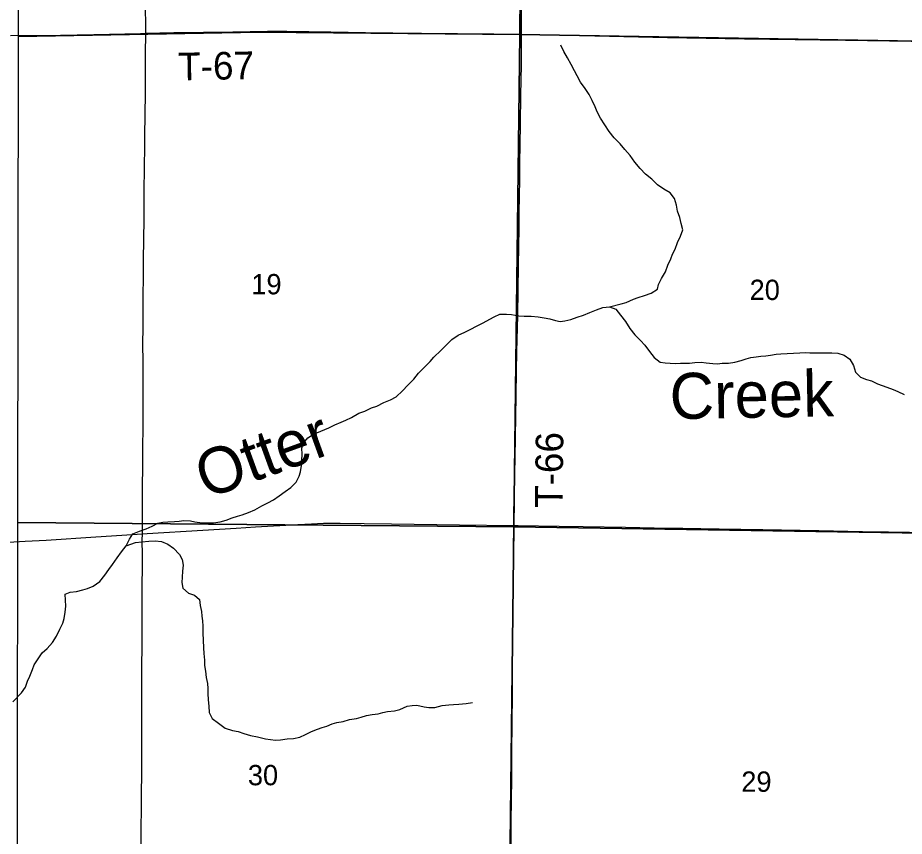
# Model space of a CAD drawing. Extents: x 0 to 45.9, y 0 to 22.
# Drawn here: x 5.48 to 7.305, y 15.053 to 16.738 of the extents above; entities that cross this region are included whole.
import ezdxf

# ---------------------------------------------------------------- set-up
doc = ezdxf.new("R2010")
doc.units = 0
for name, color, linetype in [('GM_X_County_Road', 7, 'Continuous'), ('GM_X_Minor_River', 7, 'Continuous'), ('GM_X_Minor_River_Text', 7, 'Continuous'), ('GM_X_Section', 7, 'Continuous'), ('GM_X_Section_Text', 7, 'Continuous'), ('GM_X_State_Route', 7, 'Continuous'), ('GM_X_Township_Road', 7, 'Continuous'), ('GM_X_Township_Road_Text', 7, 'Continuous')]:
    doc.layers.add(name, color=color, linetype=linetype)

msp = doc.modelspace()

# ---------------------------------------------------------------- linework, layer by layer
at = {"layer": 'GM_X_County_Road'}
msp.add_lwpolyline([(6.4922, 14.6848), (6.4925, 14.7031), (6.4931, 14.7497), (6.4935, 14.7963), (6.4943, 14.9175), (6.495, 14.9858), (6.496, 15.079), (6.4964, 15.1318), (6.497, 15.166), (6.4974, 15.1877), (6.4974, 15.225), (6.4976, 15.2871), (6.4982, 15.343), (6.4985, 15.3834), (6.4988, 15.4145), (6.499, 15.4642), (6.4995, 15.5077), (6.5001, 15.5667), (6.5003, 15.6009), (6.5006, 15.6413), (6.5009, 15.6926)], dxfattribs=at)
at = {"layer": 'GM_X_Minor_River'}
for points in [[(6.6979, 16.1429), (6.7221, 16.1487), (6.7324, 16.1517), (6.7475, 16.1582), (6.7574, 16.1621), (6.7699, 16.1663), (6.7839, 16.1705), (6.7967, 16.1789), (6.799, 16.1884), (6.8054, 16.2009), (6.8133, 16.215), (6.8182, 16.2283), (6.8242, 16.2416), (6.8276, 16.251), (6.8333, 16.2613), (6.8381, 16.275), (6.8442, 16.2883), (6.8487, 16.3012), (6.8456, 16.3141), (6.8425, 16.3266), (6.8383, 16.3394), (6.836, 16.3523), (6.8317, 16.366), (6.8226, 16.3777), (6.8101, 16.3852), (6.7971, 16.3939), (6.7853, 16.4056), (6.7724, 16.4158), (6.761, 16.4276), (6.7499, 16.4404), (6.7404, 16.454), (6.7297, 16.4669), (6.7198, 16.4786), (6.708, 16.4903), (6.6977, 16.5036), (6.6886, 16.5176), (6.6798, 16.5308), (6.6729, 16.5444), (6.6683, 16.5543), (6.6622, 16.5675), (6.6561, 16.5797), (6.6481, 16.5925), (6.6386, 16.605), (6.6313, 16.6183), (6.6263, 16.6285), (6.6195, 16.6414), (6.6118, 16.6554), (6.6042, 16.6686), (6.5977, 16.6811)], [(5.47, 15.3291), (5.4883, 15.3481), (5.4962, 15.3598), (5.5007, 15.372), (5.5049, 15.3819), (5.5105, 15.3959), (5.5143, 15.4054), (5.5222, 15.418), (5.5305, 15.4301), (5.5407, 15.4389), (5.552, 15.4518), (5.56, 15.4647), (5.5671, 15.4788), (5.5731, 15.4917), (5.5761, 15.5012), (5.578, 15.5141), (5.5791, 15.5262), (5.5783, 15.5384), (5.5782, 15.5513), (5.5881, 15.5551), (5.6014, 15.5563), (5.6146, 15.5597), (5.6241, 15.5628), (5.6358, 15.5678), (5.6491, 15.5773), (5.6593, 15.5902), (5.668, 15.6016), (5.6751, 15.6119), (5.685, 15.6256), (5.694, 15.6385), (5.7038, 15.6507), (5.7102, 15.664), (5.717, 15.6754), (5.731, 15.6811), (5.7447, 15.6857), (5.7572, 15.6911), (5.7689, 15.6972), (5.7788, 15.6995), (5.7894, 15.6999), (5.8027, 15.7007), (5.8125, 15.7015), (5.822, 15.7027), (5.8357, 15.7019), (5.8451, 15.7001), (5.8599, 15.6982), (5.8732, 15.6979), (5.8835, 15.6979), (5.8967, 15.6999), (5.9092, 15.7033), (5.9217, 15.7079), (5.9327, 15.7114), (5.9422, 15.7144), (5.9551, 15.719), (5.9683, 15.7248), (5.9824, 15.7328), (5.9952, 15.7393), (6.0066, 15.7454), (6.0183, 15.7538), (6.0308, 15.7625), (6.0422, 15.7705), (6.0531, 15.7819), (6.0595, 15.7937), (6.0621, 15.8032), (6.064, 15.8161), (6.0651, 15.8263), (6.0654, 15.8392), (6.065, 15.8518), (6.0676, 15.8616), (6.0771, 15.873), (6.0892, 15.8807), (6.104, 15.8864), (6.1202, 15.8937), (6.1327, 15.8994), (6.1456, 15.9055), (6.1555, 15.9093), (6.1672, 15.9147), (6.1823, 15.9238), (6.1949, 15.9277), (6.2081, 15.9345), (6.2195, 15.9384), (6.2335, 15.9456), (6.2471, 15.9514), (6.2592, 15.9571), (6.2721, 15.9696), (6.283, 15.9814), (6.2951, 15.9936), (6.305, 16.0058), (6.3288, 16.0298), (6.3363, 16.0393), (6.3511, 16.053), (6.3734, 16.0754), (6.3866, 16.0842), (6.4003, 16.0907), (6.4366, 16.109), (6.4605, 16.1224), (6.4722, 16.1273), (6.4859, 16.1278), (6.4965, 16.1267), (6.5113, 16.1244), (6.5227, 16.1233), (6.5367, 16.1238)], [(6.5367, 16.1238), (6.5511, 16.1219), (6.5637, 16.1201), (6.5754, 16.1178), (6.5868, 16.1148), (6.5963, 16.1126), (6.6065, 16.1138), (6.6187, 16.1168), (6.6316, 16.1211), (6.6444, 16.1256), (6.6577, 16.131), (6.6713, 16.1367), (6.6846, 16.141), (6.6979, 16.1429), (6.7108, 16.1376), (6.7207, 16.1255), (6.731, 16.1123), (6.7398, 16.0983), (6.7504, 16.085), (6.7622, 16.0737), (6.771, 16.0635), (6.7805, 16.0506), (6.79, 16.0382), (6.8026, 16.0287), (6.8125, 16.0276), (6.8227, 16.0265), (6.8329, 16.0262), (6.8439, 16.0266), (6.8629, 16.027), (6.8735, 16.0278), (6.8864, 16.0286), (6.8967, 16.0275), (6.9107, 16.026), (6.9202, 16.0253), (6.9297, 16.0265), (6.9433, 16.0269), (6.9558, 16.0285), (6.9687, 16.0319), (6.979, 16.0358), (6.9888, 16.0384), (6.9998, 16.04), (7.0097, 16.0412), (7.0199, 16.042), (7.0294, 16.0431), (7.0408, 16.0451), (7.0506, 16.0459), (7.0635, 16.0467), (7.0764, 16.0471), (7.0897, 16.0483), (7.1007, 16.0487), (7.1106, 16.0483), (7.12, 16.048), (7.1322, 16.0477), (7.142, 16.0481), (7.1553, 16.0477), (7.1678, 16.047), (7.1807, 16.0433), (7.1925, 16.035), (7.2002, 16.0221), (7.2044, 16.0085), (7.2147, 15.9979), (7.2272, 15.9934), (7.2375, 15.99), (7.2496, 15.9843), (7.2591, 15.981), (7.269, 15.9776), (7.2819, 15.9727), (7.2914, 15.9685), (7.3047, 15.9621)], [(5.7038, 15.6507), (5.7228, 15.6576), (5.7357, 15.6587), (5.7501, 15.6603), (5.763, 15.6607), (5.7759, 15.6593), (5.7892, 15.654), (5.801, 15.6457), (5.8131, 15.6328), (5.8185, 15.6222), (5.8208, 15.6105), (5.8197, 15.5987), (5.8186, 15.5858), (5.8179, 15.5752), (5.8198, 15.5635), (5.832, 15.5533), (5.8442, 15.5487), (5.8541, 15.5401), (5.856, 15.5279), (5.8583, 15.5154), (5.8595, 15.5059), (5.8603, 15.4965), (5.8611, 15.4855), (5.8611, 15.4707), (5.8616, 15.4563), (5.8628, 15.4407), (5.8632, 15.4286), (5.8644, 15.4153), (5.8648, 15.4043), (5.8664, 15.3926), (5.8683, 15.3797), (5.8706, 15.3668), (5.8718, 15.3566), (5.8718, 15.3467), (5.8723, 15.3334), (5.8738, 15.3202), (5.8746, 15.3076), (5.8807, 15.2951), (5.8937, 15.2853), (5.907, 15.2755), (5.9222, 15.2706), (5.9339, 15.2684), (5.9457, 15.2639), (5.959, 15.2598), (5.9738, 15.2575), (5.9905, 15.253), (6.011, 15.2508), (6.0212, 15.2512), (6.0349, 15.2532), (6.0478, 15.2536), (6.0611, 15.2567), (6.0724, 15.262), (6.0849, 15.2685), (6.097, 15.2731), (6.1069, 15.2766), (6.1164, 15.2796), (6.1273, 15.2842), (6.1368, 15.2869), (6.1501, 15.2888), (6.163, 15.2927), (6.1774, 15.2954), (6.1869, 15.2977), (6.1978, 15.3011), (6.2096, 15.3035), (6.2217, 15.305), (6.2316, 15.3077), (6.2414, 15.3096), (6.2555, 15.3108), (6.2665, 15.3135), (6.2816, 15.3204), (6.2922, 15.3219), (6.3017, 15.3224), (6.3165, 15.3194), (6.326, 15.3175), (6.3389, 15.3175), (6.3537, 15.3218), (6.3673, 15.323), (6.3772, 15.3241), (6.3882, 15.3249), (6.403, 15.3257), (6.4159, 15.3277)]]:
    msp.add_lwpolyline(points, dxfattribs=at)
at = {"layer": 'GM_X_Section'}
for points in [[(5.4835, 17.7031), (6.0871, 17.7131), (6.5217, 17.7114), (6.5134, 16.7036), (5.9766, 16.7084), (5.4822, 16.699)], [(6.5217, 17.7114), (7.5472, 17.6966), (7.5363, 16.6862), (6.5134, 16.7036)], [(5.4822, 16.699), (5.9766, 16.7084), (6.5134, 16.7036), (6.5014, 15.6897), (5.4804, 15.6984)], [(6.5134, 16.7036), (7.5363, 16.6862), (7.5224, 15.6742), (6.5014, 15.6897)], [(6.5014, 15.6897), (6.4893, 14.6816), (5.4789, 14.694), (5.4804, 15.6984)], [(7.5224, 15.6742), (7.4967, 14.6639), (6.4893, 14.6816), (6.5014, 15.6897)]]:
    msp.add_lwpolyline(points, close=True, dxfattribs=at)
at = {"layer": 'GM_X_State_Route'}
for points in [[(5.4608, 15.6583), (5.4954, 15.6601), (5.5388, 15.6625), (5.6411, 15.6689), (5.7368, 15.6752), (5.7466, 15.6758), (5.8613, 15.6831), (5.9296, 15.6871), (5.9699, 15.6896), (6.0567, 15.6947), (6.0847, 15.6962), (6.1095, 15.6971), (6.1437, 15.6972), (6.1935, 15.6966), (6.2494, 15.6956), (6.296, 15.695), (6.3892, 15.6938), (6.5009, 15.6926), (6.5104, 15.6925), (6.5943, 15.6913), (6.644, 15.6902), (6.731, 15.6888), (6.79, 15.6877), (6.849, 15.6867), (6.9236, 15.6853), (7.0137, 15.684), (7.1287, 15.682), (7.2187, 15.6802), (7.2685, 15.6796), (7.2725, 15.6795)], [(7.2725, 15.6795), (7.3586, 15.6779), (7.4145, 15.677), (7.4334, 15.6767)]]:
    msp.add_lwpolyline(points, dxfattribs=at)
at = {"layer": 'GM_X_Township_Road'}
for points in [[(6.5172, 16.7037), (6.5172, 16.7187), (6.5168, 16.7871), (6.5162, 16.8586), (6.516, 17.0047), (6.516, 17.0544), (6.5154, 17.0917), (6.5158, 17.1135), (6.5158, 17.1321), (6.5155, 17.1445), (6.5154, 17.1694), (6.5162, 17.2066), (6.5163, 17.2101), (6.5164, 17.2377), (6.5169, 17.2781), (6.5179, 17.3403), (6.5183, 17.3807), (6.5196, 17.4491), (6.5211, 17.5673), (6.5223, 17.6419), (6.5236, 17.7071), (6.5237, 17.7143)], [(5.7436, 16.7061), (5.7436, 16.728), (5.7435, 16.7529), (5.7438, 16.7809), (5.7443, 16.815), (5.7449, 16.8647), (5.7453, 16.9051), (5.7458, 16.9611), (5.746, 17.0015), (5.7462, 17.0387), (5.7465, 17.0947), (5.7468, 17.1537), (5.7468, 17.1879), (5.7469, 17.2044)], [(5.4653, 16.7013), (5.5685, 16.7021), (5.6369, 16.7037), (5.7332, 16.7058), (5.7436, 16.7061)], [(5.7385, 16.1598), (5.7385, 16.1658), (5.7389, 16.2031), (5.7391, 16.2187), (5.7394, 16.2434), (5.7398, 16.2775), (5.7403, 16.3272), (5.7408, 16.3707), (5.7412, 16.4391), (5.7416, 16.4639), (5.7422, 16.495), (5.743, 16.582), (5.7432, 16.6379), (5.7434, 16.669), (5.7436, 16.7001), (5.7436, 16.7061)], [(5.7436, 16.7061), (5.8015, 16.7077), (5.9227, 16.7089), (5.994, 16.7101), (6.0344, 16.71), (6.1245, 16.7091), (6.196, 16.7078), (6.2519, 16.7071), (6.3109, 16.7062), (6.4601, 16.7046), (6.5172, 16.7037)], [(6.5009, 15.6926), (6.501, 15.699), (6.5015, 15.7208), (6.5025, 15.7674), (6.5039, 15.8327), (6.5054, 15.9166), (6.5061, 15.9602), (6.5067, 16.0099), (6.5075, 16.0503), (6.5093, 16.1249), (6.5102, 16.1777), (6.511, 16.2275), (6.5121, 16.3052), (6.5123, 16.3207), (6.5125, 16.3363), (6.5133, 16.4047), (6.5138, 16.4389), (6.5144, 16.4762), (6.5152, 16.5197), (6.5159, 16.5788), (6.5169, 16.6409), (6.5172, 16.6689), (6.5172, 16.7037)], [(6.5172, 16.7037), (6.5315, 16.7034), (6.5906, 16.7026), (6.6682, 16.7007), (6.8174, 16.6975), (6.9758, 16.6945), (7.184, 16.6915), (7.3642, 16.689), (7.4574, 16.6876), (7.5369, 16.6872), (7.5398, 16.6872)], [(5.7368, 15.6752), (5.7368, 15.6811), (5.7369, 15.7152), (5.7371, 15.7712), (5.7375, 15.8147), (5.7382, 15.9327), (5.7383, 16.0322), (5.738, 16.0632), (5.7383, 16.1036), (5.7385, 16.1598)], [(6.4922, 14.6848), (6.4925, 14.7031), (6.4931, 14.7497), (6.4935, 14.7963), (6.4943, 14.9175), (6.495, 14.9858), (6.496, 15.079), (6.4964, 15.1318), (6.497, 15.166), (6.4974, 15.1877), (6.4974, 15.225), (6.4976, 15.2871), (6.4982, 15.343), (6.4985, 15.3834), (6.4988, 15.4145), (6.499, 15.4642), (6.4995, 15.5077), (6.5001, 15.5667), (6.5003, 15.6009), (6.5006, 15.6413), (6.5009, 15.6926)], [(5.7321, 14.6921), (5.7322, 14.7241), (5.7325, 14.8017), (5.7329, 14.8483), (5.7336, 14.9322), (5.7339, 14.9851), (5.7341, 15.0223), (5.7345, 15.0565), (5.7349, 15.1218), (5.7355, 15.1995), (5.7355, 15.2492), (5.7358, 15.3424), (5.736, 15.4014), (5.7362, 15.4449), (5.7365, 15.5444), (5.7368, 15.6314), (5.7367, 15.6624), (5.7368, 15.6752)]]:
    msp.add_lwpolyline(points, dxfattribs=at)

# ---------------------------------------------------------------- texts
at = {"layer": 'GM_X_Minor_River_Text'}
for s, rotation, p in [('Creek', 1.0804, (6.8227, 15.9112)), ('Otter', 19.9751, (5.8677, 15.7464))]:
    msp.add_text(s, height=0.09472, rotation=rotation, dxfattribs=at).set_placement(p)
at = {"layer": 'GM_X_Section_Text'}
for s, p in [('19', (5.961, 16.1684)), ('20', (6.9864, 16.1567)), ('30', (5.9539, 15.1576)), ('29', (6.9693, 15.1442))]:
    msp.add_text(s, height=0.04186, rotation=0, dxfattribs=at).set_placement(p)
at = {"layer": 'GM_X_Township_Road_Text'}
for s, rotation, p in [('T-67', 1.0663, (5.8108, 16.6089)), ('T-66', 89.2952, (6.6013, 15.7283))]:
    msp.add_text(s, height=0.05682, rotation=rotation, dxfattribs=at).set_placement(p)

doc.saveas('drawing.dxf')
